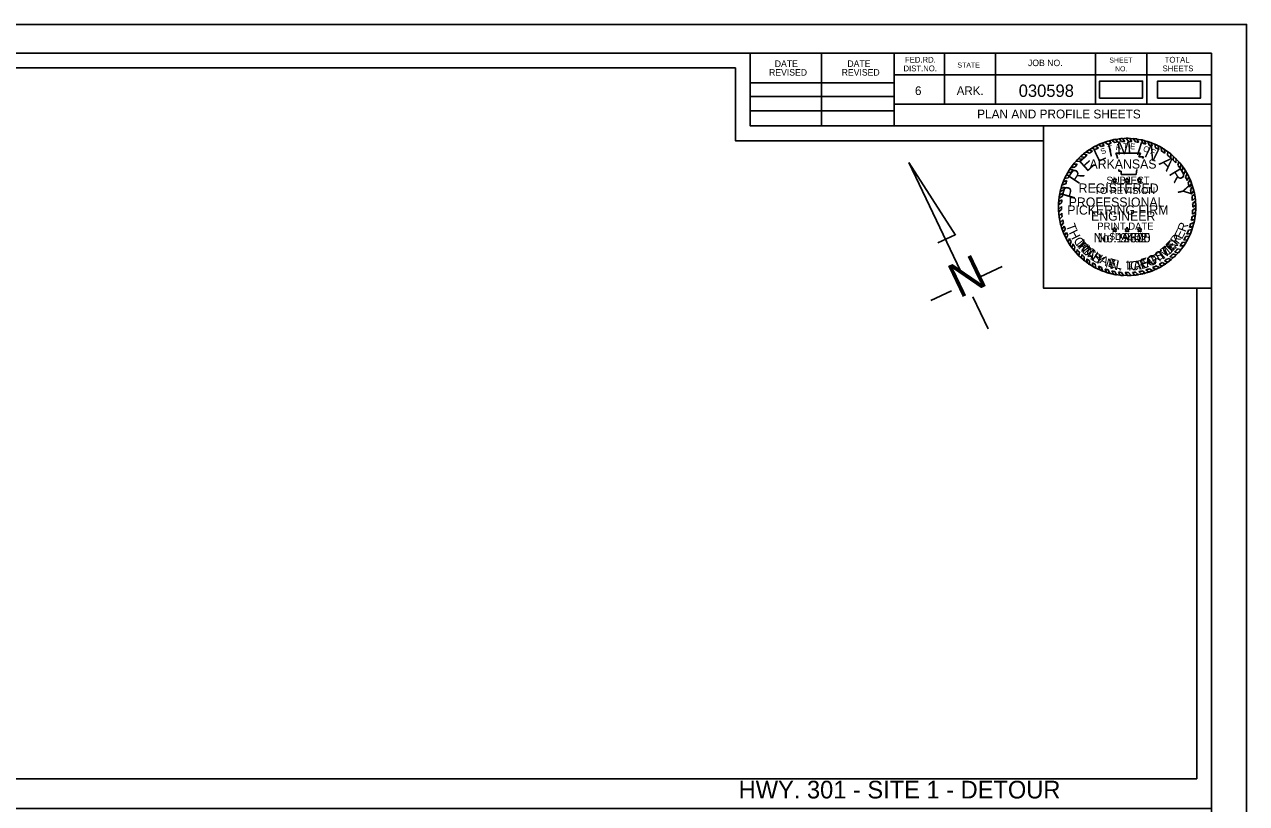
# Model space of a CAD drawing. Extents: x 816090 to 819714, y 1801340 to 1803641.
# Drawn here: x 818885 to 819714, y 1803112 to 1803641 of the extents above; entities that cross this region are included whole.
import ezdxf

# ---------------------------------------------------------------- set-up
doc = ezdxf.new("R2010")
doc.units = 0
for name, color, linetype in [('R_Border', 7, 'Continuous'), ('R_Border Notes', 7, 'Continuous'), ('R_Border Title', 7, 'Continuous'), ('R_Draft', 7, 'Continuous'), ('R_No Plot', 7, 'Continuous'), ('R_Vert Alg Annot', 7, 'Continuous'), ('STAMP_PE_CRAFTON', 7, 'Continuous'), ('STAMP_PE_FOSTER', 7, 'Continuous'), ('STAMP_PE_SEAL-INFO', 7, 'Continuous'), ('STAMP_PE_TAEGTMEYER', 7, 'Continuous'), ('STAMP_PE_TXT', 7, 'Continuous'), ('STAMP_PRELIMINARY', 7, 'Continuous')]:
    doc.layers.add(name, color=color, linetype=linetype)

msp = doc.modelspace()

# ---------------------------------------------------------------- linework, layer by layer
at = {"layer": 'R_Border'}
for p, q in [((818109.59, 1803621.13), (819690.49, 1803621.13)), ((819377.29, 1803571.73), (819377.29, 1803621.13)), ((819425.69, 1803571.73), (819425.69, 1803621.13)), ((819474.99, 1803621.13), (819474.99, 1803571.73)), ((819509.19, 1803621.13), (819509.19, 1803586.43)), ((819543.89, 1803621.13), (819543.89, 1803586.43)), ((819611.79, 1803621.13), (819611.79, 1803586.43)), ((819646.49, 1803621.13), (819646.49, 1803586.43)), ((819690.49, 1802593.83), (819690.49, 1803621.13)), ((819690.49, 1803606.43), (819474.99, 1803606.43)), ((819690.49, 1803606.53), (819690.49, 1803606.53)), ((819377.29, 1803601.03), (819474.99, 1803601.03)), ((819377.29, 1803591.73), (819474.99, 1803591.73)), ((819690.49, 1803586.43), (819474.99, 1803586.43)), ((819489.79, 1803586.43), (819690.49, 1803586.43)), ((819377.29, 1803582.03), (819474.99, 1803582.03)), ((819690.49, 1803571.73), (819377.29, 1803571.73))]:
    msp.add_line(p, q, dxfattribs=at)
at = {"layer": 'R_Draft'}
for p, q in [((819484.95, 1803546.87), (819516.6, 1803497.51)), ((819520.02, 1803473.46), (819484.95, 1803546.87)), ((819504.75, 1803492.33), (819516.42, 1803497.9)), ((819533.42, 1803469.24), (819548.29, 1803476.34)), ((819500.01, 1803453.28), (819513.93, 1803459.93)), ((819538.82, 1803434.09), (819528.51, 1803455.67))]:
    msp.add_line(p, q, dxfattribs=at)
at = {"layer": 'R_No Plot'}
msp.add_line((818047.58, 1803640.6), (819714.25, 1803640.6), dxfattribs=at)
for points in [[(818047.58, 1803640.62), (819714.28, 1803640.62), (819714.28, 1802573.94), (818047.58, 1802573.94)], [(819377.29, 1803621.13), (819377.29, 1803571.73), (819457.85, 1803571.73), (819576.4, 1803571.73), (819576.4, 1803461.73), (819690.49, 1803461.73), (819690.49, 1803108.53), (818109.59, 1803108.53), (818109.59, 1803621.13)], [(819680.49, 1803128.53), (818119.59, 1803128.53), (818119.59, 1803611.13), (819367.29, 1803611.13), (819367.29, 1803561.73), (819576.4, 1803561.73), (819576.4, 1803461.73), (819680.49, 1803461.73)], [(819680.49, 1803128.53), (818119.59, 1803128.53), (818119.59, 1803611.13), (819367.29, 1803611.13), (819367.29, 1803561.73), (819576.4, 1803561.73), (819576.4, 1803461.73), (819680.49, 1803461.73)], [(819680.49, 1803128.53), (818119.59, 1803128.53), (818119.59, 1803611.13), (819367.29, 1803611.13), (819367.29, 1803561.73), (819576.4, 1803561.73), (819576.4, 1803461.73), (819680.49, 1803461.73)], [(819690.49, 1803571.73), (819576.4, 1803571.73), (819576.4, 1803461.73), (819690.49, 1803461.73)]]:
    msp.add_lwpolyline(points, close=True, dxfattribs=at)
at = {"layer": 'R_Vert Alg Annot'}
for points in [[(819614.55, 1803590.65), (819643.72, 1803590.65), (819643.72, 1803602.2), (819614.55, 1803602.2)], [(819653.9, 1803590.65), (819683.07, 1803590.65), (819683.07, 1803602.2), (819653.9, 1803602.2)]]:
    msp.add_lwpolyline(points, close=True, dxfattribs=at)
at = {"layer": 'STAMP_PE_SEAL-INFO'}
for p, q in [((819617.98, 1803560.79), (819619.88, 1803559.27)), ((819620.93, 1803561.7), (819622.37, 1803559.97)), ((819622.87, 1803562.19), (819624.65, 1803560.47)), ((819625.28, 1803562.67), (819626.78, 1803560.83)), ((819627.86, 1803563.04), (819629.27, 1803561.12)), ((819631.54, 1803561.27), (819629.98, 1803563.23)), ((819634.03, 1803561.29), (819632.63, 1803563.34)), ((819636.32, 1803561.19), (819635.03, 1803563.31)), ((819638.85, 1803560.93), (819637.39, 1803563.15)), ((819640.98, 1803560.61), (819639.69, 1803562.89)), ((819643.79, 1803560.02), (819642.92, 1803562.31)), ((819645.8, 1803559.47), (819645, 1803561.82)), ((819648.05, 1803558.74), (819647.35, 1803561.14)), ((819603.38, 1803552.58), (819606.03, 1803552.07)), ((819605.27, 1803554.21), (819607.55, 1803553.19)), ((819607.37, 1803555.55), (819609.58, 1803554.53)), ((819609.31, 1803556.76), (819611.47, 1803555.65)), ((819611.55, 1803558.02), (819613.86, 1803556.89)), ((819613.7, 1803559.08), (819615.65, 1803557.7)), ((819616.24, 1803560.15), (819617.71, 1803558.53)), ((819625.54, 1803553.19), (819642.27, 1803553.19)), ((819626.15, 1803551.65), (819625.54, 1803553.19)), ((819642.27, 1803553.19), (819641.14, 1803550.73)), ((819650.15, 1803557.94), (819649.42, 1803560.42)), ((819652.45, 1803556.91), (819651.94, 1803559.4)), ((819654.68, 1803555.77), (819654.25, 1803558.31)), ((819656.62, 1803554.64), (819656.42, 1803557.14)), ((819658.79, 1803553.2), (819658.64, 1803555.78)), ((819660.59, 1803551.87), (819660.77, 1803554.3)), ((819662.83, 1803550.01), (819662.92, 1803552.62)), ((819596.65, 1803545.68), (819599.39, 1803545.79)), ((819598.38, 1803547.74), (819600.98, 1803547.54)), ((819599.99, 1803549.46), (819602.71, 1803549.25)), ((819601.67, 1803551.08), (819603.96, 1803550.38)), ((819626.67, 1803550.16), (819626.15, 1803551.65)), ((819626.71, 1803549.59), (819626.67, 1803550.16)), ((819641.14, 1803550.73), (819644.3, 1803550.73)), ((819644.3, 1803550.73), (819643.58, 1803549.59)), ((819664.39, 1803548.54), (819664.74, 1803551.04)), ((819666.18, 1803546.68), (819666.52, 1803549.31)), ((819667.55, 1803545.1), (819668.24, 1803547.45)), ((819669.17, 1803543.01), (819669.85, 1803545.51)), ((819590.76, 1803536.05), (819593.27, 1803536.56)), ((819591.7, 1803537.99), (819594.19, 1803538.31)), ((819592.85, 1803540.11), (819595.3, 1803540.21)), ((819594.08, 1803542.11), (819596.66, 1803542.28)), ((819595.26, 1803543.83), (819597.78, 1803543.81)), ((819627.66, 1803541.04), (819627.53, 1803542.13)), ((819629.23, 1803541.04), (819627.66, 1803541.04)), ((819629.23, 1803538.89), (819629.23, 1803541.04)), ((819639.38, 1803538.89), (819629.23, 1803538.89)), ((819639.46, 1803540.58), (819639.38, 1803538.89)), ((819639.85, 1803542.13), (819639.46, 1803540.58)), ((819670.27, 1803541.43), (819671.16, 1803543.75)), ((819671.81, 1803538.95), (819672.73, 1803541.4)), ((819672.81, 1803537.12), (819673.94, 1803539.34)), ((819673.97, 1803534.69), (819675.1, 1803537.12)), ((819587.78, 1803527.3), (819590.13, 1803528.26)), ((819588.3, 1803529.34), (819590.69, 1803530.18)), ((819589.09, 1803531.85), (819591.51, 1803532.53)), ((819589.84, 1803533.88), (819592.36, 1803534.61)), ((819674.67, 1803533.01), (819675.99, 1803535.18)), ((819675.64, 1803530.26), (819677, 1803532.64)), ((819676.18, 1803528.44), (819677.65, 1803530.7)), ((819676.85, 1803525.65), (819678.44, 1803527.88)), ((819588.7, 1803519.47), (819586.59, 1803518.19)), ((819588.88, 1803521.6), (819586.7, 1803520.19)), ((819589.17, 1803523.77), (819586.95, 1803522.66)), ((819589.6, 1803526.07), (819587.27, 1803524.82)), ((819677.19, 1803523.75), (819678.96, 1803525.51)), ((819677.52, 1803521.2), (819679.39, 1803522.88)), ((819677.68, 1803519.11), (819679.64, 1803520.57)), ((819588.61, 1803517), (819586.59, 1803515.33)), ((819588.65, 1803514.97), (819586.69, 1803513.35)), ((819588.81, 1803512.49), (819586.96, 1803510.71)), ((819677.24, 1803510.02), (819679.45, 1803511.12)), ((819677.49, 1803511.96), (819679.66, 1803513.25)), ((819677.69, 1803514.5), (819679.79, 1803515.88)), ((819677.75, 1803516.52), (819679.77, 1803518.13)), ((819589.07, 1803510.35), (819587.3, 1803508.48)), ((819589.47, 1803508.05), (819587.77, 1803506.21)), ((819589.93, 1803505.96), (819588.37, 1803503.88)), ((819590.55, 1803503.72), (819589.08, 1803501.63)), ((819675.51, 1803502.79), (819677.96, 1803503.8)), ((819676.25, 1803505.26), (819678.61, 1803506.27)), ((819676.79, 1803507.52), (819679.06, 1803508.5)), ((819591.26, 1803501.61), (819589.85, 1803499.55)), ((819592.09, 1803499.48), (819590.78, 1803497.36)), ((819592.95, 1803497.56), (819591.81, 1803495.25)), ((819594.12, 1803495.27), (819593.17, 1803492.82)), ((819671.6, 1803494.15), (819674.11, 1803494.42)), ((819672.96, 1803496.64), (819675.4, 1803496.98)), ((819673.77, 1803498.32), (819676.21, 1803498.8)), ((819674.84, 1803500.89), (819677.25, 1803501.55)), ((819595.3, 1803493.25), (819594.38, 1803490.89)), ((819596.31, 1803491.69), (819595.76, 1803488.93)), ((819597.72, 1803489.74), (819597.21, 1803487.08)), ((819599.24, 1803487.85), (819598.8, 1803485.25)), ((819600.75, 1803486.16), (819600.44, 1803483.55)), ((819665.59, 1803486.14), (819667.98, 1803485.71)), ((819667.51, 1803488.3), (819669.81, 1803487.91)), ((819669.05, 1803490.27), (819671.57, 1803490.29)), ((819670.74, 1803492.74), (819673.13, 1803492.71)), ((819602.36, 1803484.54), (819602.21, 1803481.89)), ((819604.08, 1803482.97), (819604.07, 1803480.33)), ((819605.88, 1803481.5), (819605.98, 1803478.88)), ((819607.57, 1803480.25), (819607.76, 1803477.66)), ((819609.71, 1803478.84), (819610.01, 1803476.28)), ((819611.46, 1803477.81), (819611.92, 1803475.25)), ((819654.84, 1803477.78), (819656.92, 1803476.62)), ((819656.91, 1803479), (819659.16, 1803478.03)), ((819658.63, 1803480.14), (819660.82, 1803479.2)), ((819660.93, 1803481.86), (819663.27, 1803481.13)), ((819662.29, 1803482.98), (819664.64, 1803482.34)), ((819664.32, 1803484.84), (819666.52, 1803484.15)), ((819613.87, 1803476.56), (819614.65, 1803473.96)), ((819615.73, 1803475.72), (819616.59, 1803473.17)), ((819618.19, 1803474.76), (819619.24, 1803472.25)), ((819620.24, 1803474.08), (819621.37, 1803471.64)), ((819622.78, 1803473.39), (819623.84, 1803471.06)), ((819624.77, 1803472.96), (819626, 1803470.67)), ((819627.27, 1803472.56), (819628.47, 1803470.35)), ((819629.45, 1803472.32), (819630.82, 1803470.18)), ((819631.87, 1803472.18), (819633.39, 1803470.12)), ((819634.17, 1803472.17), (819635.89, 1803470.19)), ((819636.77, 1803472.31), (819638.4, 1803470.41)), ((819638.96, 1803472.54), (819640.82, 1803470.75)), ((819641.18, 1803472.89), (819643.13, 1803471.19)), ((819643.65, 1803473.41), (819645.54, 1803471.78)), ((819645.94, 1803474.03), (819648.03, 1803472.54)), ((819648.41, 1803474.84), (819650.62, 1803473.5)), ((819650.5, 1803475.67), (819652.62, 1803474.36)), ((819652.8, 1803476.71), (819655.22, 1803475.65))]:
    msp.add_line(p, q, dxfattribs=at)
for radius, start, end in [(46.61, 105.23389, 109.03519), (46.61, 99.75254, 102.77648), (44.57, 98.25799, 101.03289), (46.61, 93.93815, 96.55172), (44.57, 92.11016, 95.03666), (46.61, 87.72979, 90.67067), (44.57, 85.96279, 88.9097), (46.61, 81.97315, 84.82355), (44.57, 79.92642, 82.69597), (46.61, 75.31251, 77.94263), (46.61, 69.60611, 72.30577), (46.61, 129.73259, 132.53764), (46.61, 123.61993, 126.59063), (44.57, 121.97456, 125.11001), (46.61, 117.65441, 120.80988), (44.57, 115.68692, 119.15827), (46.61, 111.31242, 114.70259), (44.57, 110.30864, 113.16588), (44.57, 104.03521, 107.36155), (44.57, 73.55748, 76.23144), (44.57, 67.62483, 70.50398), (46.61, 63.13288, 66.2704), (44.57, 61.15575, 64.37837), (46.61, 56.90029, 60.09423), (44.57, 54.92383, 58.27016), (46.61, 50.3492, 53.71593), (46.61, 141.60556, 144.44865), (44.57, 139.30101, 142.58729), (46.61, 135.40208, 138.30314), (44.57, 133.13306, 136.25623), (44.57, 127.52969, 130.96829), (44.57, 48.30163, 52.03953), (44.57, 42.22116, 45.55119), (46.61, 44.3405, 47.39292), (44.57, 36.13503, 39.53106), (46.61, 38.12472, 41.23157), (46.61, 152.86398, 155.51889), (46.61, 147.00719, 149.89904), (44.57, 151.03153, 153.57304), (44.57, 145.01972, 148.21036), (44.57, 29.90321, 33.66454), (46.61, 31.96138, 35.42937), (44.57, 23.77322, 27.22114), (46.61, 25.93909, 29.01247), (46.61, 164.3068, 166.89395), (46.61, 158.40766, 161.07015), (44.57, 162.43309, 165.00133), (44.57, 156.34018, 159.23194), (44.57, 17.68022, 21.42509), (46.61, 19.95381, 23.31409), (44.57, 11.54445, 15.23639), (46.61, 13.84205, 17.44468), (46.61, 175.74093, 178.2066), (46.61, 170.0003, 172.68778), (44.57, 173.73, 176.47337), (44.57, 167.90481, 170.90393), (44.57, 5.7599, 9.06056), (44.57, 359.73289, 3.06392), (46.61, 7.58519, 10.86211), (46.61, 1.72155, 4.72681), (46.61, 181.72508, 184.16255), (44.57, 179.64537, 182.26333), (44.57, 185.45389, 188.23401), (44.57, 353.86319, 357.12742), (46.61, 349.83047, 353.08845), (46.61, 355.71562, 358.95694), (46.61, 187.42037, 190.19271), (46.61, 193.03695, 195.99732), (44.57, 191.22736, 193.98583), (44.57, 196.96751, 199.83526), (44.57, 341.77699, 345.09248), (44.57, 348.07782, 351.34355), (46.61, 343.89247, 347.03502), (46.61, 198.89671, 201.62812), (46.61, 204.54793, 207.43282), (44.57, 202.77613, 205.47915), (44.57, 208.78826, 211.79343), (44.57, 329.55488, 333.20757), (44.57, 335.6038, 339.18578), (46.61, 331.40371, 334.93315), (46.61, 337.38367, 340.99332), (46.61, 210.86355, 213.65709), (46.61, 216.61154, 219.49098), (44.57, 214.18375, 217.27474), (44.57, 220.39088, 223.30564), (44.57, 316.65308, 320.37109), (46.61, 318.28455, 321.80429), (44.57, 323.58513, 327.44069), (46.61, 325.44052, 328.98725), (46.61, 222.47995, 225.38008), (46.61, 228.36648, 231.34802), (44.57, 226.24938, 229.24068), (44.57, 232.22904, 234.93361), (46.61, 234.29502, 236.94517), (44.57, 238.22227, 240.83529), (44.57, 299.07679, 302.17235), (46.61, 300.62101, 303.87026), (44.57, 304.82299, 308.51428), (46.61, 306.37206, 310.20799), (44.57, 310.77436, 314.31605), (46.61, 312.45177, 315.66328), (46.61, 240.1977, 242.86128), (44.57, 244.32043, 246.94859), (46.61, 246.57598, 249.15579), (44.57, 250.34912, 253.12157), (46.61, 252.59667, 255.32518), (44.57, 256.50505, 259.11916), (46.61, 258.44328, 261.13983), (44.57, 262.37828, 265.20115), (46.61, 264.19784, 267.10092), (44.57, 268.3215, 271.27698), (46.61, 270.25484, 273.33609), (44.57, 274.61565, 277.44863), (46.61, 276.42389, 279.43574), (44.57, 280.34588, 283.58137), (46.61, 282.31994, 285.37019), (44.57, 286.64233, 289.97826), (46.61, 288.57086, 291.97334), (44.57, 292.87452, 296.11851), (46.61, 294.64808, 298.21662)]:
    msp.add_arc((819633.18, 1803516.73), radius, start, end, dxfattribs=at)
at = {"layer": 'STAMP_PE_TXT'}
for p, q in [((819624.31, 1803535.31), (819624.69, 1803536.47)), ((819624.69, 1803536.47), (819625.07, 1803535.31)), ((819632.8, 1803535.31), (819633.18, 1803536.47)), ((819633.18, 1803536.47), (819633.56, 1803535.31)), ((819641.29, 1803535.31), (819641.67, 1803536.47)), ((819641.67, 1803536.47), (819642.05, 1803535.31)), ((819624.08, 1803534.59), (819623.09, 1803535.31)), ((819623.09, 1803535.31), (819624.31, 1803535.31)), ((819623.7, 1803533.42), (819624.08, 1803534.59)), ((819624.69, 1803534.14), (819623.7, 1803533.42)), ((819625.68, 1803533.42), (819624.69, 1803534.14)), ((819625.07, 1803535.31), (819626.3, 1803535.31)), ((819626.3, 1803535.31), (819625.3, 1803534.59)), ((819625.3, 1803534.59), (819625.68, 1803533.42)), ((819632.57, 1803534.59), (819631.58, 1803535.31)), ((819631.58, 1803535.31), (819632.8, 1803535.31)), ((819632.19, 1803533.42), (819632.57, 1803534.59)), ((819633.18, 1803534.14), (819632.19, 1803533.42)), ((819634.17, 1803533.42), (819633.18, 1803534.14)), ((819633.56, 1803535.31), (819634.79, 1803535.31)), ((819634.79, 1803535.31), (819633.79, 1803534.59)), ((819633.79, 1803534.59), (819634.17, 1803533.42)), ((819641.06, 1803534.59), (819640.07, 1803535.31)), ((819640.07, 1803535.31), (819641.29, 1803535.31)), ((819640.68, 1803533.42), (819641.06, 1803534.59)), ((819641.67, 1803534.14), (819640.68, 1803533.42)), ((819642.66, 1803533.42), (819641.67, 1803534.14)), ((819642.05, 1803535.31), (819643.27, 1803535.31)), ((819643.27, 1803535.31), (819642.28, 1803534.59)), ((819642.28, 1803534.59), (819642.66, 1803533.42)), ((819624.31, 1803501.77), (819624.69, 1803502.94)), ((819624.69, 1803502.94), (819625.07, 1803501.77)), ((819632.8, 1803501.77), (819633.18, 1803502.94)), ((819633.18, 1803502.94), (819633.56, 1803501.77)), ((819641.29, 1803501.77), (819641.67, 1803502.94)), ((819641.67, 1803502.94), (819642.05, 1803501.77)), ((819624.08, 1803501.05), (819623.09, 1803501.77)), ((819623.09, 1803501.77), (819624.31, 1803501.77)), ((819623.7, 1803499.89), (819624.08, 1803501.05)), ((819624.69, 1803500.61), (819623.7, 1803499.89)), ((819625.68, 1803499.89), (819624.69, 1803500.61)), ((819625.07, 1803501.77), (819626.3, 1803501.77)), ((819626.3, 1803501.77), (819625.3, 1803501.05)), ((819625.3, 1803501.05), (819625.68, 1803499.89)), ((819632.57, 1803501.05), (819631.58, 1803501.77)), ((819631.58, 1803501.77), (819632.8, 1803501.77)), ((819632.19, 1803499.89), (819632.57, 1803501.05)), ((819633.18, 1803500.61), (819632.19, 1803499.89)), ((819634.17, 1803499.89), (819633.18, 1803500.61)), ((819633.56, 1803501.77), (819634.79, 1803501.77)), ((819634.79, 1803501.77), (819633.79, 1803501.05)), ((819633.79, 1803501.05), (819634.17, 1803499.89)), ((819641.06, 1803501.05), (819640.07, 1803501.77)), ((819640.07, 1803501.77), (819641.29, 1803501.77)), ((819640.68, 1803499.89), (819641.06, 1803501.05)), ((819641.67, 1803500.61), (819640.68, 1803499.89)), ((819642.66, 1803499.89), (819641.67, 1803500.61)), ((819642.05, 1803501.77), (819643.27, 1803501.77)), ((819643.27, 1803501.77), (819642.28, 1803501.05)), ((819642.28, 1803501.05), (819642.66, 1803499.89))]:
    msp.add_line(p, q, dxfattribs=at)
at = {"layer": 'STAMP_PRELIMINARY'}
msp.add_circle((819633.18, 1803516.73), 46.61, dxfattribs=at)

# ---------------------------------------------------------------- texts
at = {"layer": 'R_Border'}
for s, height, p in [('TOTAL', 3.91, (819658.69, 1803614.73)), ('REVISED', 4.396, (819390.08, 1803605.91)), ('DATE', 4.396, (819393.98, 1803611.81)), ('REVISED', 4.396, (819439.38, 1803605.91)), ('DATE', 4.396, (819443.28, 1803611.81)), ('DIST.NO.', 3.91, (819481.39, 1803608.83)), ('FED.RD.', 3.91, (819482.39, 1803614.73)), ('STATE', 3.42, (819517.99, 1803611.33)), ('JOB NO.', 4.396, (819565.89, 1803612.33)), ('SHEET', 3.42, (819621.09, 1803614.73)), ('NO.', 3.42, (819624.99, 1803608.83)), ('SHEETS', 3.91, (819657.29, 1803608.83)), ('6', 5.86, (819489.19, 1803592.73)), ('ARK.', 5.861, (819517.49, 1803592.73))]:
    msp.add_text(s, height=height, dxfattribs=at).set_placement(p)
at = {"layer": 'R_Border Notes'}
for s, height, p in [('030598', 8.4, (819559.59, 1803591.46)), ('PLAN AND PROFILE SHEETS', 6, (819531.4, 1803576.83))]:
    msp.add_text(s, height=height, dxfattribs=at).set_placement(p)
at = {"layer": 'R_Border Title'}
msp.add_text('HWY. 301 - SITE 1 - DETOUR', height=12, dxfattribs=at).set_placement((819369.46, 1803115.28))
at = {"layer": 'R_Draft'}
msp.add_text('N', height=23.27, rotation=25.53194, dxfattribs=at).set_placement((819519.28, 1803454.54))
at = {"layer": 'STAMP_PE_CRAFTON'}
for s, rotation, p in [('T', 310.74416, (819598.01, 1803491.22)), ('N', 49.24107, (819664.59, 1803486.84)), ('O', 317.64216, (819601.35, 1803487.16)), ('N', 324.45371, (819605.58, 1803483.24)), ('T', 34.11362, (819656.06, 1803479.92)), ('O', 41.83906, (819660.36, 1803482.93)), ('Y', 331.16864, (819610.74, 1803479.66)), ('N', 347.47515, (819621.01, 1803475.08)), ('C', 6.01169, (819635.54, 1803473.44)), ('R', 14.81888, (819641.02, 1803474.01)), ('A', 20.51248, (819646.58, 1803475.51)), ('F', 28.78207, (819651.49, 1803477.38)), ('.', 356.89262, (819627.16, 1803473.69))]:
    msp.add_text(s, height=6.25, rotation=rotation, dxfattribs=at).set_placement(p)
msp.add_text('No. 12370', height=6.25, dxfattribs=at).set_placement((819610.49, 1803492.71))
at = {"layer": 'STAMP_PE_FOSTER'}
for s, rotation, p in [('M', 308.33902, (819598.76, 1803491.84)), ('E', 46.96131, (819663.18, 1803486.68)), ('R', 54.5031, (819666.8, 1803490.78)), ('I', 314.18423, (819602.75, 1803487.15)), ('C', 319.87327, (819604.52, 1803485.39)), ('H', 327.72349, (819609.17, 1803481.7)), ('S', 31.72336, (819654.13, 1803479.79)), ('T', 39.41938, (819658.89, 1803482.93)), ('A', 335.72761, (819614.07, 1803478.79)), ('E', 343.5779, (819619.76, 1803476.44)), ('L', 350.81148, (819625.05, 1803475.06)), ('L', 1.26658, (819632.75, 1803474.27)), ('F', 15.86908, (819643.36, 1803475.5)), ('O', 23.71897, (819648.58, 1803477.14)), ('.', 6.80354, (819637.98, 1803474.56))]:
    msp.add_text(s, height=6, rotation=rotation, dxfattribs=at).set_placement(p)
msp.add_text('No. 9402', height=6.25, dxfattribs=at).set_placement((819613.11, 1803492.71))
at = {"layer": 'STAMP_PE_TAEGTMEYER'}
for s, rotation, p in [('T', 289.64597, (819591.65, 1803504.28)), ('R', 69.57001, (819672.91, 1803499.3)), ('H', 296.73386, (819593.45, 1803499.36)), ('O', 303.77078, (819596.42, 1803493.82)), ('Y', 53.99864, (819667.07, 1803489.69)), ('E', 63.0984, (819670.41, 1803494.39)), ('M', 314.20329, (819599.69, 1803489.06)), ('A', 321.0594, (819604.5, 1803484.24)), ('T', 31.46601, (819653.68, 1803478.5)), ('M', 39.30005, (819658.17, 1803481.22)), ('E', 46.80938, (819663.37, 1803485.62)), ('S', 327.82385, (819608.63, 1803481.02)), ('N', 344.27273, (819618.11, 1803475.99)), ('T', 3.00609, (819632.5, 1803473.33)), ('A', 8.98261, (819637.73, 1803473.61)), ('E', 17.68363, (819642.93, 1803474.39)), ('G', 23.30524, (819648.18, 1803476.04)), ('.', 350.64643, (819624.18, 1803474.33))]:
    msp.add_text(s, height=6.25, rotation=rotation, dxfattribs=at).set_placement(p)
msp.add_text('No. 19605', height=6.25, dxfattribs=at).set_placement((819610.49, 1803492.71))
at = {"layer": 'STAMP_PE_TXT'}
for s, rotation, p in [('S', 23.5541, (819616.17, 1803552.25)), ('T', 16.311, (819620.79, 1803554.11)), ('A', 9.0679, (819625.6, 1803555.37)), ('T', 1.82479, (819630.53, 1803556.02)), ('E', 355.20019, (819635.08, 1803556.06)), ('O', 342.25065, (819643.72, 1803554.68)), ('F', 335.00755, (819648.54, 1803552.99))]:
    msp.add_text(s, height=3.91, rotation=rotation, dxfattribs=at).set_placement(p)
for s, p in [('ARKANSAS', (819607.64, 1803542.78)), ('REGISTERED', (819600.26, 1803526.43)), ('PROFESSIONAL', (819593.52, 1803516.93)), ('ENGINEER', (819608.72, 1803507.42))]:
    msp.add_text(s, height=6.25, dxfattribs=at).set_placement(p)
at = {"layer": 'STAMP_PRELIMINARY'}
for s, rotation, p in [('M', 3.10738, (819626.36, 1803552.21)), ('I', 342.31637, (819638.7, 1803552.54)), ('L', 25.51305, (819613.22, 1803546.87)), ('I', 12.52485, (819620.87, 1803550.66)), ('N', 333.9382, (819644.23, 1803551.17)), ('E', 42.35784, (819605.81, 1803540.21)), ('A', 315.65789, (819654.4, 1803546.05)), ('R', 56.22922, (819600.03, 1803531.55)), ('R', 301.38306, (819661.24, 1803539.48)), ('P', 73.91301, (819597.29, 1803521.43)), ('Y', 283.25926, (819666.69, 1803530.54))]:
    msp.add_text(s, height=9, rotation=rotation, dxfattribs=at).set_placement(p)
for s, height, p in [('SUBJECT', 4.8, (819619.18, 1803532.48)), ('TO REVISION', 4.8, (819610.86, 1803525.55)), ('PICKERING FIRM', 6.25, (819592.55, 1803511.55)), ('PRINT DATE', 4.8, (819612.97, 1803501.31)), ('$DATE$', 4.8, (819621.35, 1803494.38))]:
    msp.add_text(s, height=height, dxfattribs=at).set_placement(p)

doc.saveas('drawing.dxf')
